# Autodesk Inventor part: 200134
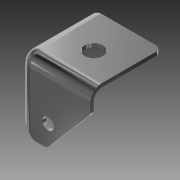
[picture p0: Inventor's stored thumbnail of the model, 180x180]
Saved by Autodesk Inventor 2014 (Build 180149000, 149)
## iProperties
Created: 2007-10
Part Number: 200134
Document SubType Name: Modeling
Designer: TH
Density: 7.85 g/cm^3
Mass: 90.2441 g
Surface Area: 99.9897 cm^2
Volume: 11.4961 cm^3
Material: Steel
Description: CORNER BRACKET
Appearance: Steel - Polished
Component Category: Lower Component
Author: TH
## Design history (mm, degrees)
sketch "Sketch1"
  geometry: L1 (-25, 25)-(25, 25); L2 (25, 25)-(25, -25); L3 (25, -25)-(-25, -25); L4 (-25, -25)-(-25, 25); 1 further point
  constraints: 8 end point, 2 parallel, 1 horizontal, 1 perpendicular
  dimensions: "d0" = 50 distance of L3.end L1.start (= d1); "d1" = 50 distance of L1.start L1.end; "d2" = 25 distance from line of point (0, 0) L4 (= 0.5 x d1); "d3" = 25 distance from line of point (0, 0) L1 (= 0.5 x d0)
extrude "Extrusion1" new body sketch "Sketch1" distance "d4" = 50; taper "d5" = 0 deg
fillet "Fillet1" dims "d6" = 8.5
shell "Shell1" dims "d7" = 2.5
sketch "Sketch2"
  geometry: L1 (0, 41.5)-(-41.5, 41.5) reference; L2 (-41.5, 41.5)-(-41.5, 0) reference; L3 (-41.5, 6.5)-(-6.5, 6.5); L4 (-6.5, 6.5)-(-6.5, 41.5); L5 (-6.5, 41.5)-(-41.5, 41.5); L6 (-41.5, 41.5)-(-41.5, 6.5); 1 further point
  constraints: 8 end point, 2 parallel, 2 point on line, 1 horizontal, 1 perpendicular
  dimensions: "d8" = 35 distance of L3.start L3.end; "d9" = 35 distance from line of L3 L1.start
extrude "Extrusion2" cut sketch "Sketch2" stored distance "d10" = 26.136; taper "d11" = 0 deg
sketch "Sketch3"
  geometry: L1 (41.5, 0)-(41.5, 2.5) reference; L2 (41.5, 15)-(11.5, 50); L3 (0, 50)-(41.5, 50) reference; L4 (41.5, 50)-(11.5, 50); L5 (41.5, 50)-(41.5, 15); 5 further points
  constraints: 7 end point, 2 collinear, 2 point on line
  dimensions: "d36" = 30 distance of L3.end L2.end; "d37" = 35 distance of L3.end L2.start
extrude "Extrusion3" cut sketch "Sketch3" stored distance "d14" = 26.136; taper "d15" = 0 deg
sketch "Sketch4"
  geometry: L1 (-5, -25)-(25, -25) reference; L2 (-16.5, -25)-(25, -25) reference; L3 (-16.5, -25)-(-5, -25) reference; L4 (-25, 25)-(-25, -10) reference; L5 (-25, 25)-(-25, -16.5) reference; L6 (-25, -10)-(-25, -16.5) reference; 2 further points
  dimensions: "d17" = 27.606 distance from line of point (2.606, 0) L5; "d18" = 25 distance from line of L2 point (2.606, 0)
hole "Hole1" sketch "Sketch4" at (2.606, 0) diameter "d19" = 12.8; stored, may be unused: countersink angle "d23" = 90 deg, drill point angle "d25" = 118 deg; dims "d20" = 6, "d21" = 4, "d22" = 2, "d24" = 8
sketch "Sketch5"
  geometry: L1 (12.706, 8.5)-(25.506, 8.5) reference; L2 (0, 8.5)-(41.5, 8.5) reference; L3 (41.5, 8.5)-(0, 8.5) reference; L4 (-8.5, -6.5)-(-8.5, -41.5) reference; 2 further points
  dimensions: "d43" = 20.785 distance from line of point (12.285, -26.5) L4; "d44" = 35 distance from line of point (12.285, -26.5) L1
hole "Hole2" sketch "Sketch5" at (12.285, -26.5) diameter "d28" = 8; stored, may be unused: countersink angle "d32" = 90 deg, drill point angle "d34" = 118 deg; dims "d29" = 6, "d30" = 4, "d31" = 2, "d33" = 8
sketch "Sketch6"
  geometry: L1 (0, 50)-(11.5, 50) reference; L2 (-8.5, 15)-(-8.5, 50) reference; L3 (2, 50)-(-8.5, 40); L4 (-8.5, 40)-(-8.5, 50); L5 (-8.5, 50)-(2, 50); A1 r 8.5 centre (0, 8.5) between (-8.5, 8.5) and (0, 0) reference; 4 further points
  constraints: 6 end point, 3 point on line, 1 collinear, 1 perpendicular
  dimensions: "d38" = 2 horizontal distance of L3.start A1.centre; "d39" = 40 vertical distance of L3.end A1.end
extrude "Extrusion4" cut sketch "Sketch6" stored distance "d40" = 10; taper "d41" = 0 deg
fillet "Fillet3" dims "d42" = 4
body "Solid1"
node "Projected Loop1"
node "Projected Loop2"
node "Projected Loop3"
